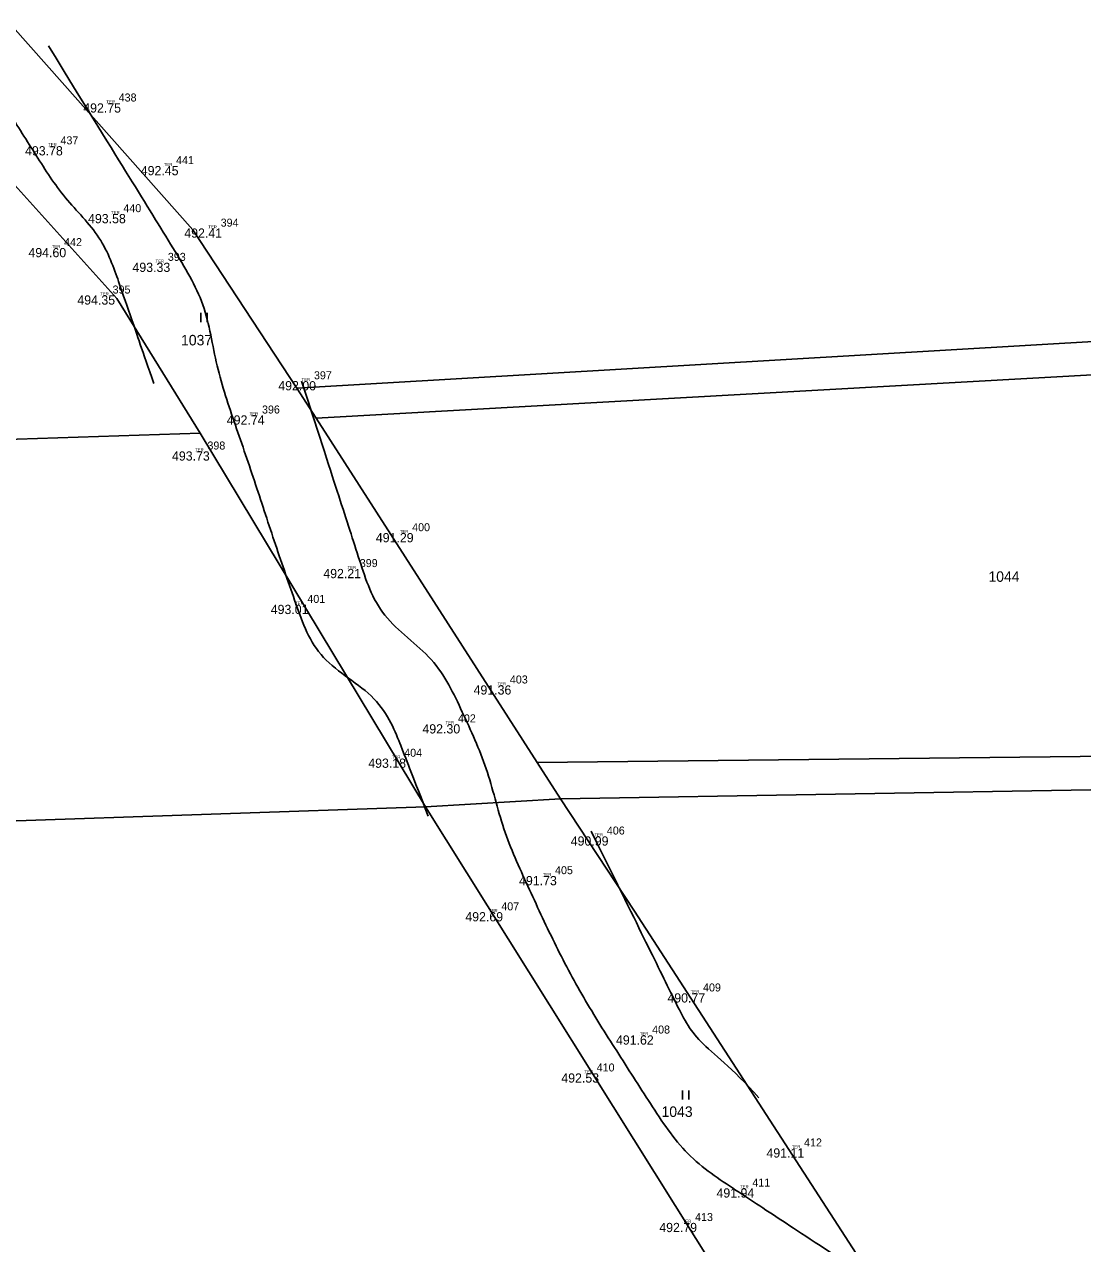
# Model space of a CAD drawing. Extents: x -604848 to -603227, y -1111879 to -1109838.
# Drawn here: x -604117.6 to -603945.6, y -1110187.8 to -1109989.7 of the extents above; entities that cross this region are included whole.
import ezdxf

# ---------------------------------------------------------------- set-up
doc = ezdxf.new("R2010")
doc.units = 0
for name, color, linetype in [('1', 7, 'Continuous'), ('14', 7, 'Continuous'), ('18', 7, 'Continuous'), ('19', 7, 'Continuous'), ('20', 7, 'Continuous'), ('23', 7, 'Continuous'), ('7', 7, 'Continuous'), ('Default', 7, 'Continuous')]:
    doc.layers.add(name, color=color, linetype=linetype)

# ---------------------------------------------------------------- blocks, each defined once
blk = doc.blocks.new('Z3060')
at = {"layer": '23'}
for p, q in [((-0.5, 0), (-0.5, 1.5)), ((0.5, 1.5), (0.5, 0))]:
    blk.add_line(p, q, dxfattribs=at)
blk = doc.blocks.new('POINT_DISPLAY')
at = {"layer": 'Default'}
blk.add_line((0, 0), (0, 0), dxfattribs=at)

msp = doc.modelspace()

# ---------------------------------------------------------------- linework, layer by layer
at = {"layer": '1'}
for p, q in [((-604102.57, -1110034.26), (-604195.43, -1109931.12)), ((-604147.03, -1109959.11), (-604090.17, -1110023.09)), ((-604090.17, -1110023.09), (-604073.27, -1110048.8)), ((-604089.01, -1110056.15), (-604102.57, -1110034.26)), ((-604073.27, -1110048.8), (-603884.88, -1110037.82)), ((-604070.16, -1110053.69), (-603884.46, -1110043.32)), ((-604070.16, -1110053.69), (-604073.27, -1110048.8)), ((-604034.25, -1110109.65), (-604070.16, -1110053.69)), ((-604179.11, -1110059.09), (-604089.01, -1110056.15)), ((-604089.01, -1110056.15), (-604052.4, -1110116.85)), ((-603928.34, -1110108.45), (-604034.25, -1110109.65)), ((-604030.45, -1110115.56), (-604034.25, -1110109.65)), ((-603842.9, -1110112.36), (-604030.45, -1110115.56)), ((-604052.4, -1110116.85), (-604030.45, -1110115.56)), ((-604030.45, -1110115.56), (-604018.44, -1110133.77)), ((-604052.4, -1110116.85), (-604211.8, -1110122.23)), ((-603973.97, -1110241.87), (-604052.4, -1110116.85)), ((-604018.44, -1110133.77), (-603977.54, -1110196.88))]:
    msp.add_line(p, q, dxfattribs=at)
at = {"layer": '7'}
for points in [[(-604096.53, -1110048.04), (-604098.4, -1110042.67), (-604100.25, -1110037.29), (-604102.12, -1110031.91), (-604104.84, -1110024.09), (-604111.2, -1110018.05), (-604115.63, -1110011.05), (-604120.2, -1110003.83), (-604124.7, -1109996.56), (-604129.28, -1109989.34), (-604134.06, -1109981.81), (-604139.33, -1109974.7), (-604145.1, -1109967.77), (-604151.28, -1109960.36), (-604158.5, -1109953.74), (-604166.92, -1109949.27), (-604174.06, -1109945.49), (-604181.2, -1109941.71), (-604188.34, -1109937.93)], [(-604051.93, -1110118.34), (-604053.3, -1110114.84), (-604054.66, -1110111.34), (-604056.03, -1110107.84), (-604059.61, -1110098.65), (-604070.16, -1110093.22), (-604073.42, -1110083.91), (-604076.81, -1110074.23), (-604079.95, -1110064.48), (-604083.29, -1110054.79), (-604086.56, -1110045.33), (-604087.93, -1110034.97), (-604093.18, -1110026.45), (-604100, -1110015.37), (-604106.83, -1110004.3), (-604113.65, -1109993.22)], [(-603979.46, -1110193.91), (-603986.93, -1110189), (-603994.4, -1110184.09), (-604001.86, -1110179.18), (-604010.17, -1110173.72), (-604015.87, -1110165.03), (-604021.29, -1110156.53), (-604026.82, -1110147.85), (-604031.5, -1110138.95), (-604035.76, -1110129.71), (-604039.98, -1110120.54), (-604042.18, -1110110.5), (-604046.42, -1110101.41), (-604050.58, -1110092.48), (-604060.04, -1110086.25), (-604063.09, -1110076.83), (-604066.23, -1110067.12), (-604069.37, -1110057.4), (-604072.51, -1110047.68)], [(-603998.22, -1110164.1), (-604002.66, -1110159.06), (-604008.57, -1110155.02), (-604011.54, -1110149), (-604016.18, -1110139.59), (-604020.82, -1110130.18), (-604025.47, -1110120.78)]]:
    msp.add_open_spline(points, degree=3, dxfattribs=at)

# ---------------------------------------------------------------- block references
at = {"layer": '18'}
for p in [(-604104.24, -1110002.55), (-604113.7, -1110009.51), (-604094.92, -1110012.73), (-604103.48, -1110020.53), (-604087.67, -1110022.88), (-604113.11, -1110026.05), (-604096.25, -1110028.44), (-604105.23, -1110033.75), (-604072.51, -1110047.68), (-604080.95, -1110053.24), (-604089.82, -1110059.09), (-604056.55, -1110072.36), (-604065.06, -1110078.19), (-604073.58, -1110084.02), (-604040.67, -1110097.1), (-604049.11, -1110103.42), (-604057.84, -1110109), (-604024.91, -1110121.64), (-604033.33, -1110128.08), (-604042.06, -1110133.95), (-604009.28, -1110147.13), (-604017.55, -1110153.97), (-604026.56, -1110160.14), (-603992.86, -1110172.32), (-604001.26, -1110178.82), (-604010.57, -1110184.43)]:
    msp.add_blockref('POINT_DISPLAY', p, dxfattribs=at)
at = {"layer": '23'}
for p in [(-604088.39, -1110038.09), (-604010.1, -1110164.4)]:
    msp.add_blockref('Z3060', p, dxfattribs=at)

# ---------------------------------------------------------------- texts
at = {"layer": '14'}
for s, p in [('1037', (-604092.11, -1110041.87)), ('1044', (-603960.9, -1110080.28)), ('1043', (-604014.03, -1110167.21))]:
    msp.add_text(s, height=1.7, dxfattribs=at).set_placement(p)
at = {"layer": '18'}
for p in [(-604104.24, -1110002.55), (-604113.7, -1110009.51), (-604094.92, -1110012.73), (-604103.48, -1110020.53), (-604087.67, -1110022.88), (-604113.11, -1110026.05), (-604096.25, -1110028.44), (-604105.23, -1110033.75), (-604072.51, -1110047.68), (-604080.95, -1110053.24), (-604089.82, -1110059.09), (-604056.55, -1110072.36), (-604065.06, -1110078.19), (-604073.58, -1110084.02), (-604040.67, -1110097.1), (-604049.11, -1110103.42), (-604057.84, -1110109), (-604024.91, -1110121.64), (-604033.33, -1110128.08), (-604042.06, -1110133.95), (-604009.28, -1110147.13), (-604017.55, -1110153.97), (-604026.56, -1110160.14), (-603992.86, -1110172.32), (-604001.26, -1110178.82), (-604010.57, -1110184.43)]:
    msp.add_text('TER', height=0.5, dxfattribs=at).set_placement(p)
at = {"layer": '19'}
for s, p in [('438', (-604102.24, -1110002.25)), ('437', (-604111.7, -1110009.21)), ('441', (-604092.92, -1110012.43)), ('440', (-604101.48, -1110020.23)), ('394', (-604085.67, -1110022.58)), ('442', (-604111.11, -1110025.75)), ('393', (-604094.25, -1110028.14)), ('395', (-604103.23, -1110033.45)), ('397', (-604070.51, -1110047.38)), ('396', (-604078.95, -1110052.94)), ('398', (-604087.82, -1110058.79)), ('400', (-604054.55, -1110072.06)), ('399', (-604063.06, -1110077.89)), ('401', (-604071.58, -1110083.71)), ('403', (-604038.67, -1110096.8)), ('402', (-604047.11, -1110103.12)), ('404', (-604055.84, -1110108.7)), ('406', (-604022.91, -1110121.34)), ('405', (-604031.33, -1110127.78)), ('407', (-604040.06, -1110133.65)), ('409', (-604007.28, -1110146.83)), ('408', (-604015.55, -1110153.67)), ('410', (-604024.56, -1110159.83)), ('412', (-603990.86, -1110172.02)), ('411', (-603999.26, -1110178.52)), ('413', (-604008.57, -1110184.13))]:
    msp.add_text(s, height=1.3, dxfattribs=at).set_placement(p)
at = {"layer": '20'}
for s, p in [('492.75 ', (-604108, -1110004.05)), ('493.78 ', (-604117.46, -1110011.01)), ('492.45 ', (-604098.65, -1110014.23)), ('493.58 ', (-604107.22, -1110022.03)), ('492.41 ', (-604091.58, -1110024.38)), ('494.60 ', (-604116.91, -1110027.55)), ('493.33 ', (-604100, -1110029.94)), ('494.35 ', (-604108.96, -1110035.25)), ('492.00 ', (-604076.31, -1110049.18)), ('492.74 ', (-604084.67, -1110054.74)), ('493.73 ', (-604093.58, -1110060.59)), ('491.29 ', (-604060.45, -1110073.86)), ('492.21 ', (-604068.99, -1110079.69)), ('493.01 ', (-604077.53, -1110085.52)), ('491.36 ', (-604044.57, -1110098.6)), ('492.30 ', (-604052.88, -1110104.92)), ('493.18 ', (-604061.68, -1110110.5)), ('490.99 ', (-604028.78, -1110123.14)), ('491.73 ', (-604037.18, -1110129.58)), ('492.69 ', (-604045.91, -1110135.45)), ('490.77 ', (-604013.07, -1110148.63)), ('491.62 ', (-604021.43, -1110155.47)), ('492.53 ', (-604030.31, -1110161.64)), ('491.11 ', (-603996.97, -1110173.82)), ('491.94 ', (-604005.09, -1110180.32)), ('492.79 ', (-604014.39, -1110185.93))]:
    msp.add_text(s, height=1.5, dxfattribs=at).set_placement(p)

doc.saveas('drawing.dxf')
